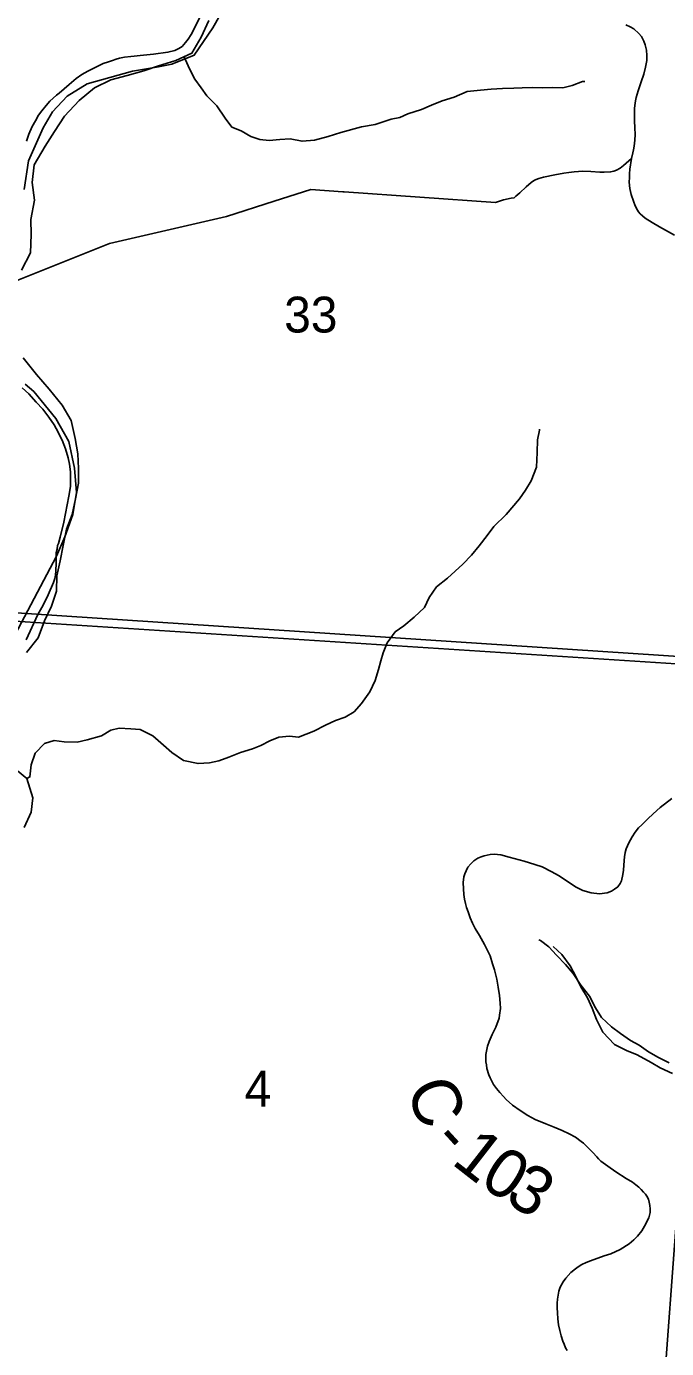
# Model space of a CAD drawing. Extents: x 0 to 34, y 0 to 22.
# Drawn here: x 3.01 to 3.758, y 18.721 to 20.265 of the extents above; entities that cross this region are included whole.
import ezdxf

# ---------------------------------------------------------------- set-up
doc = ezdxf.new("R2010")
doc.units = 0
for name, color, linetype in [('GM_X_Corporation', 7, 'Continuous'), ('GM_X_County_Road', 7, 'Continuous'), ('GM_X_County_Road_Text', 7, 'Continuous'), ('GM_X_Minor_River', 7, 'Continuous'), ('GM_X_Rail_Line', 7, 'Continuous'), ('GM_X_Section_Text', 7, 'Continuous'), ('GM_X_Township_Road', 7, 'Continuous')]:
    doc.layers.add(name, color=color, linetype=linetype)

msp = doc.modelspace()

# ---------------------------------------------------------------- linework, layer by layer
at = {"layer": 'GM_X_Corporation'}
for points in [[(6.9348, 20.9), (2.1, 20.9), (2.1, 19.6396), (2.105, 19.6393), (2.5886, 19.6074), (3.0215, 19.5789), (3.8201, 19.5262), (3.8692, 19.5228), (4.8375, 19.4557), (5.0201, 19.4401), (5.6539, 19.3859), (5.9419, 19.3649), (6.5423, 19.3229), (6.824, 19.3005), (6.835, 19.4037), (6.8961, 20.3303), (6.9032, 20.4198)], [(3.8795, 20.5363), (3.8179, 19.5177), (2.8266, 19.5815), (2.8805, 20.5967)], [(2.8266, 19.5815), (3.8179, 19.5177), (3.742, 18.4953), (2.7366, 18.558)]]:
    msp.add_lwpolyline(points, close=True, dxfattribs=at)
msp.add_lwpolyline([(6.7043, 17.4985), (6.7536, 18.2991), (6.7629, 18.3924), (6.7876, 18.7583), (6.824, 19.3005), (6.5423, 19.3229), (5.9419, 19.3649), (5.6539, 19.3859), (5.0201, 19.4401), (4.8375, 19.4557), (3.8692, 19.5228), (3.8201, 19.5262), (3.0215, 19.5789), (2.5886, 19.6074), (2.105, 19.6393), (2.1, 19.6396), (2.1, 16.1353)], dxfattribs=at)
at = {"layer": 'GM_X_County_Road'}
for points in [[(3.7677, 20.0217), (3.7501, 20.0312), (3.7416, 20.0362), (3.7334, 20.0413), (3.7303, 20.0439), (3.7276, 20.0464), (3.7258, 20.0486), (3.7245, 20.0509), (3.7216, 20.0556), (3.7197, 20.0611), (3.7172, 20.0689), (3.7156, 20.0762), (3.7149, 20.0833), (3.7151, 20.0889), (3.7151, 20.0931), (3.7155, 20.0985), (3.7174, 20.1112), (3.7189, 20.1175), (3.7196, 20.121), (3.7205, 20.1253), (3.7213, 20.1325), (3.7217, 20.1391), (3.7214, 20.1468), (3.7211, 20.155), (3.7208, 20.1624), (3.7211, 20.1698), (3.7216, 20.1757), (3.722, 20.1783), (3.7229, 20.1824), (3.7252, 20.1901), (3.7287, 20.2006), (3.7317, 20.2094), (3.7339, 20.2177), (3.7355, 20.2257), (3.7354, 20.2312), (3.7348, 20.2375), (3.7336, 20.2438), (3.7319, 20.2483), (3.729, 20.2536), (3.7261, 20.2572), (3.7201, 20.2624), (3.7158, 20.265), (3.7107, 20.2674)], [(3.6422, 18.7185), (3.6403, 18.7218), (3.6386, 18.726), (3.637, 18.7295), (3.6351, 18.7357), (3.6335, 18.7421), (3.6322, 18.7487), (3.6314, 18.7557), (3.6308, 18.7628), (3.6305, 18.7686), (3.6306, 18.7741), (3.6308, 18.7785), (3.6316, 18.7831), (3.6323, 18.7878), (3.6342, 18.7925), (3.6375, 18.7989), (3.6405, 18.8033), (3.6464, 18.8098), (3.6518, 18.814), (3.6552, 18.8164), (3.6595, 18.8189), (3.6643, 18.8214), (3.6696, 18.8235), (3.6855, 18.8294), (3.6932, 18.8316), (3.7041, 18.8366), (3.7147, 18.8434), (3.7203, 18.8479), (3.7245, 18.8523), (3.7296, 18.8583), (3.7325, 18.8638), (3.7377, 18.8737), (3.7393, 18.8799), (3.7393, 18.8841), (3.739, 18.8882), (3.7382, 18.8921), (3.7372, 18.8953), (3.7354, 18.8991), (3.7339, 18.9011), (3.7313, 18.9037), (3.7286, 18.9066), (3.726, 18.9093), (3.7224, 18.9121), (3.7188, 18.9152), (3.7111, 18.9197), (3.6991, 18.9275), (3.6897, 18.9338), (3.6816, 18.9397), (3.6787, 18.9426), (3.6768, 18.9447), (3.6721, 18.9501), (3.6682, 18.954), (3.6642, 18.9581), (3.6615, 18.9607), (3.6584, 18.9628), (3.6518, 18.9677), (3.6444, 18.9717), (3.6363, 18.9757), (3.6272, 18.9794), (3.6171, 18.9833), (3.6049, 18.9885), (3.5964, 18.9932), (3.5873, 18.9989), (3.5784, 19.0051), (3.571, 19.0119), (3.5678, 19.0152), (3.5633, 19.0202), (3.5594, 19.0247), (3.5573, 19.0277), (3.5561, 19.0294), (3.5522, 19.0371), (3.5507, 19.0407), (3.5483, 19.048), (3.5477, 19.0524), (3.5471, 19.0559), (3.547, 19.0599), (3.5472, 19.0645), (3.5482, 19.0701), (3.5492, 19.0743), (3.5511, 19.0797), (3.5546, 19.0879), (3.5587, 19.0964), (3.5626, 19.1068), (3.5632, 19.1105), (3.5641, 19.118), (3.564, 19.1245), (3.563, 19.1332), (3.5614, 19.1431), (3.5598, 19.1523), (3.5573, 19.1634), (3.555, 19.1704), (3.5521, 19.1796), (3.5455, 19.1929), (3.5396, 19.2036), (3.5346, 19.2116), (3.5316, 19.218), (3.5289, 19.2239), (3.5263, 19.2311), (3.5245, 19.2363), (3.5235, 19.2409), (3.5222, 19.246), (3.5215, 19.2514), (3.5209, 19.2578), (3.5207, 19.2653), (3.5215, 19.2721), (3.5225, 19.2754), (3.524, 19.2791), (3.5261, 19.2832), (3.5296, 19.2872), (3.533, 19.2905), (3.5377, 19.2937), (3.5416, 19.2954), (3.5452, 19.2966), (3.552, 19.2979), (3.557, 19.2984), (3.5647, 19.2976), (3.5744, 19.295), (3.5918, 19.2902), (3.6044, 19.2864), (3.6131, 19.2837), (3.6244, 19.2779), (3.6319, 19.2734), (3.6388, 19.2692), (3.646, 19.2642), (3.6526, 19.2599), (3.6607, 19.2559), (3.6701, 19.2532), (3.68, 19.2522), (3.6889, 19.2534), (3.694, 19.2553), (3.6974, 19.2574), (3.7014, 19.2604), (3.7042, 19.264), (3.7057, 19.2672), (3.7072, 19.2745), (3.7079, 19.2798), (3.7088, 19.2912), (3.7093, 19.2952), (3.7102, 19.3003), (3.7114, 19.3048), (3.7143, 19.3117), (3.7181, 19.3186), (3.7219, 19.3242), (3.7258, 19.329), (3.7294, 19.3326), (3.7366, 19.3398), (3.7429, 19.3456), (3.7509, 19.3528), (3.7646, 19.3634)]]:
    msp.add_lwpolyline(points, dxfattribs=at)
at = {"layer": 'GM_X_Minor_River'}
for points in [[(3.2232, 20.2724), (3.2144, 20.2527), (3.2034, 20.234), (3.1848, 20.2257), (3.1644, 20.2192), (3.147, 20.2136), (3.1276, 20.2079), (3.1087, 20.2029), (3.0894, 20.1935), (3.0715, 20.179), (3.0545, 20.1604), (3.0427, 20.1425), (3.0317, 20.1254), (3.0191, 20.1038), (3.0168, 20.0832), (3.0194, 20.0623), (3.0152, 20.0399), (3.0155, 20.0224), (3.0147, 20.0007), (3.0041, 19.9806)], [(3.1945, 20.23), (3.2007, 20.2159), (3.2067, 20.2037), (3.2142, 20.1938), (3.221, 20.1843), (3.2327, 20.1725), (3.2422, 20.1581), (3.2501, 20.1478), (3.261, 20.1432), (3.2724, 20.1368), (3.283, 20.1333), (3.2936, 20.1321), (3.3064, 20.1332), (3.3182, 20.1339), (3.3322, 20.1312), (3.3469, 20.1323), (3.3628, 20.1368), (3.3776, 20.1413), (3.4018, 20.1481), (3.4178, 20.1507), (3.4363, 20.157), (3.4465, 20.1589), (3.456, 20.1634), (3.4719, 20.1683), (3.4837, 20.1732), (3.4962, 20.1784), (3.5102, 20.1826), (3.5253, 20.1893), (3.5409, 20.1908), (3.5533, 20.1919), (3.5666, 20.193), (3.5798, 20.1933), (3.5897, 20.1937), (3.6018, 20.194), (3.6128, 20.1936), (3.6245, 20.1939), (3.637, 20.1935), (3.648, 20.1965), (3.6601, 20.201), (3.6627, 20.201)], [(3.0061, 19.8783), (3.0216, 19.8588), (3.0363, 19.8417), (3.0518, 19.8231), (3.0624, 19.8052), (3.0668, 19.7839), (3.0702, 19.766), (3.0709, 19.7489), (3.0709, 19.7318), (3.0674, 19.7135), (3.0632, 19.6953), (3.0568, 19.6782), (3.0529, 19.6588), (3.0495, 19.6409), (3.0453, 19.6234), (3.0452, 19.6055), (3.0391, 19.588), (3.0311, 19.5709), (3.0235, 19.5512), (3.0099, 19.5341)], [(3.0103, 19.3869), (3.014, 19.3886), (3.0155, 19.4026), (3.0201, 19.4163), (3.031, 19.4276), (3.0424, 19.4311), (3.0541, 19.4296), (3.0692, 19.4292), (3.0809, 19.4319), (3.0976, 19.4368), (3.1085, 19.4433), (3.1183, 19.4455), (3.132, 19.4448), (3.1429, 19.444), (3.1577, 19.4365), (3.1701, 19.4258), (3.18, 19.4171), (3.1936, 19.4077), (3.2106, 19.4042), (3.2238, 19.405), (3.2348, 19.4073), (3.2465, 19.4119), (3.2601, 19.4172), (3.2741, 19.4214), (3.2839, 19.4255), (3.2945, 19.4309), (3.3051, 19.435), (3.3176, 19.4362), (3.3281, 19.4351), (3.3459, 19.4423), (3.3595, 19.4491), (3.3712, 19.4544), (3.3826, 19.4586), (3.3932, 19.4647), (3.4019, 19.4746), (3.4113, 19.4882), (3.4177, 19.5011), (3.4215, 19.514), (3.4245, 19.5243), (3.4272, 19.5337), (3.4317, 19.5451), (3.4412, 19.558), (3.4514, 19.5652), (3.4635, 19.5751), (3.4752, 19.5865), (3.4809, 19.5983), (3.4896, 19.6108), (3.5024, 19.621), (3.5202, 19.637), (3.5304, 19.6476), (3.5395, 19.6586), (3.5486, 19.6708), (3.5565, 19.681), (3.5709, 19.6954), (3.5864, 19.7136), (3.5936, 19.7235), (3.6, 19.7345), (3.6064, 19.7504), (3.6072, 19.7675), (3.6076, 19.7823), (3.6098, 19.7937), (3.61, 19.7949)], [(2.9929, 19.4013), (3.0103, 19.3869), (3.0174, 19.3644), (3.0155, 19.3473), (3.0071, 19.3294)], [(3.7616, 19.0547), (3.7491, 19.0608), (3.7374, 19.0677), (3.7265, 19.0753), (3.7163, 19.0807), (3.7045, 19.0891), (3.694, 19.0967), (3.6823, 19.1077), (3.6755, 19.1191), (3.6683, 19.1324), (3.6581, 19.1454), (3.6491, 19.1591), (3.6404, 19.1697), (3.6298, 19.1804), (3.6208, 19.1903), (3.611, 19.1975), (3.6091, 19.1983)], [(3.7654, 19.0423), (3.751, 19.0488), (3.7405, 19.0552), (3.7242, 19.0639), (3.7117, 19.0692), (3.6977, 19.076), (3.6841, 19.0904), (3.6766, 19.1052), (3.6713, 19.1185), (3.666, 19.1306), (3.6581, 19.1435), (3.6528, 19.1549), (3.6456, 19.1678), (3.6358, 19.1811), (3.6257, 19.1906)]]:
    msp.add_lwpolyline(points, dxfattribs=at)
at = {"layer": 'GM_X_Rail_Line'}
for points in [[(3.0073, 20.0748), (3.0122, 20.1085), (3.0294, 20.1467), (3.0404, 20.1657), (3.0576, 20.1839), (3.0808, 20.1981), (3.134, 20.2132), (3.1644, 20.2183), (3.1801, 20.2212), (3.2061, 20.2317), (3.2278, 20.2639), (3.2688, 20.3363)], [(2.9736, 19.5122), (3.0452, 19.6466), (3.0549, 19.6691), (3.0641, 19.6951), (3.0686, 19.7209), (3.0662, 19.7492), (3.0595, 19.7804), (3.0442, 19.8074), (3.0185, 19.8389), (3.0085, 19.8476)]]:
    msp.add_lwpolyline(points, dxfattribs=at)
at = {"layer": 'GM_X_Township_Road'}
for points in [[(3.0098, 20.1312), (3.0129, 20.1395), (3.0167, 20.1485), (3.0204, 20.155), (3.0242, 20.1616), (3.0279, 20.1669), (3.0329, 20.173), (3.0374, 20.178), (3.0449, 20.1849), (3.0481, 20.1875), (3.06, 20.1977), (3.0681, 20.2046), (3.0746, 20.2091), (3.0818, 20.2132), (3.0997, 20.2219), (3.1057, 20.2241), (3.1106, 20.2257), (3.115, 20.227), (3.1189, 20.2281), (3.1247, 20.2293), (3.132, 20.2303), (3.1357, 20.2307), (3.1428, 20.2313), (3.1586, 20.2328), (3.1754, 20.2351), (3.1834, 20.2372), (3.1881, 20.2394), (3.1919, 20.2418), (3.1958, 20.2465), (3.1992, 20.2504), (3.2026, 20.2559), (3.2074, 20.2649), (3.2134, 20.2779)], [(3.3816, 20.0722), (3.5586, 20.0597), (3.5676, 20.0627), (3.5766, 20.0646), (3.5801, 20.0653), (3.5823, 20.0671), (3.5867, 20.0711), (3.5944, 20.0781), (3.6001, 20.0831), (3.6042, 20.0856), (3.6092, 20.0877), (3.6145, 20.0891), (3.6278, 20.0918), (3.6383, 20.0939), (3.6441, 20.0947), (3.6504, 20.0954), (3.6555, 20.0958), (3.6598, 20.0961), (3.6697, 20.0959), (3.6805, 20.0952), (3.6855, 20.095), (3.693, 20.0953), (3.6969, 20.0964), (3.7, 20.0974), (3.7042, 20.0998), (3.7081, 20.1027), (3.7174, 20.1112)], [(2.9823, 19.9621), (3.107, 20.0118), (3.2438, 20.0434), (3.2996, 20.0612), (3.3426, 20.0749), (3.3797, 20.0723), (3.3816, 20.0722)], [(3.0095, 19.5488), (3.0234, 19.5783), (3.0293, 19.5894), (3.0355, 19.6014), (3.0417, 19.6156), (3.0432, 19.6206), (3.044, 19.6242), (3.0444, 19.6295), (3.0445, 19.6382), (3.0445, 19.6461), (3.0447, 19.6504), (3.0457, 19.6548), (3.0464, 19.6589), (3.0474, 19.6613), (3.0492, 19.6687), (3.0535, 19.6863), (3.0594, 19.7168), (3.0614, 19.7279), (3.0616, 19.7364), (3.0615, 19.7452), (3.0604, 19.7539), (3.0586, 19.7614), (3.0554, 19.772), (3.0516, 19.7822), (3.0447, 19.7956), (3.0422, 19.7998), (3.036, 19.8089), (3.0291, 19.8183), (3.0214, 19.8266), (3.0126, 19.836), (3.005, 19.8431)]]:
    msp.add_lwpolyline(points, dxfattribs=at)

# ---------------------------------------------------------------- texts
at = {"layer": 'GM_X_County_Road_Text'}
for s, rotation, p in [('C', 291.2433, (3.4531, 19.0248)), ('-', 312.4996, (3.4821, 18.9619)), ('1', 322.0635, (3.5055, 18.9376)), ('0', 327.5759, (3.5379, 18.9127)), ('3', 327.5821, (3.5675, 18.8939))]:
    msp.add_text(s, height=0.0568, rotation=rotation, dxfattribs=at).set_placement(p)
at = {"layer": 'GM_X_Section_Text'}
for s, height, p in [('33', 0.04186, (3.3113, 19.9078)), ('4', 0.0419, (3.2651, 19.0035))]:
    msp.add_text(s, height=height, rotation=0, dxfattribs=at).set_placement(p)

doc.saveas('drawing.dxf')
